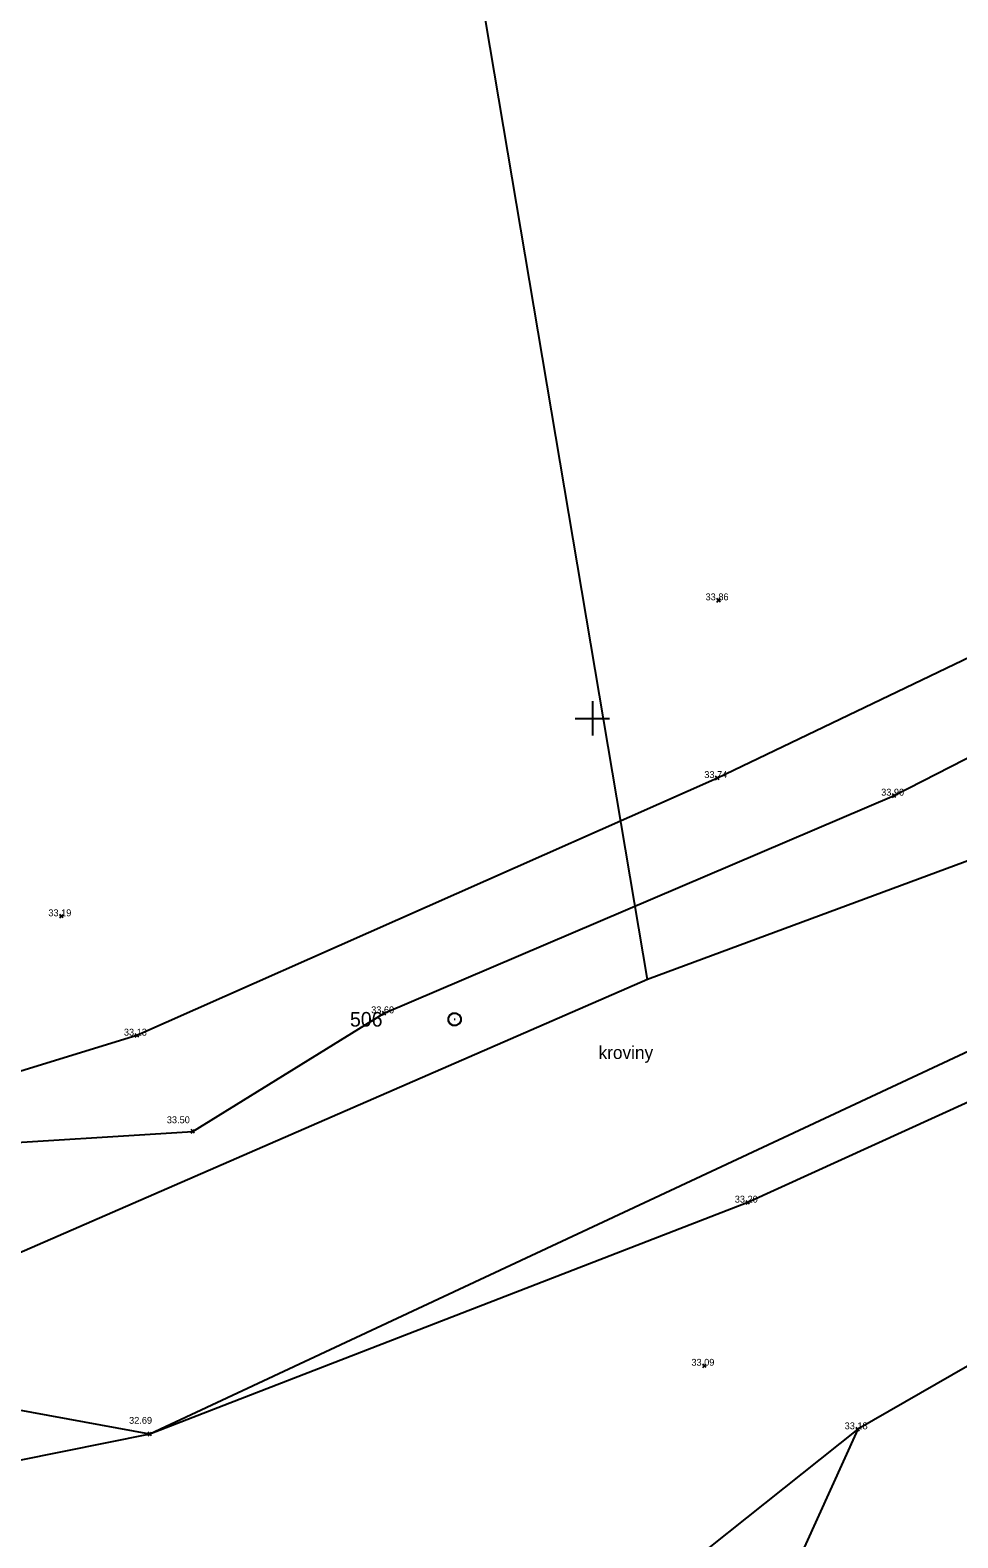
# Model space of a CAD drawing. Extents: x -772865 to -772533, y -1034366 to -1034132.
# Drawn here: x -772813.1 to -772791.49, y -1034294.09 to -1034258.97 of the extents above; entities that cross this region are included whole.
import ezdxf

# ---------------------------------------------------------------- set-up
doc = ezdxf.new("R2010")
doc.units = 0
for name, color, linetype in [('body', 7, 'Continuous'), ('KM_hranice', 7, 'Continuous'), ('KM_mezni_znaky', 7, 'Continuous'), ('mistni_popis', 7, 'Continuous'), ('oddeleni_ploch', 7, 'Continuous'), ('souradnicova_sit', 7, 'Continuous'), ('stromy_kere', 7, 'Continuous'), ('vyskove_koty', 7, 'Continuous')]:
    doc.layers.add(name, color=color, linetype=linetype)

msp = doc.modelspace()

# ---------------------------------------------------------------- linework, layer by layer
at = {"layer": 'body'}
for p, q in [((-772797.02, -1034272.29), (-772797.1, -1034272.21)), ((-772797.1, -1034272.29), (-772797.02, -1034272.21)), ((-772797.05, -1034276.43), (-772797.13, -1034276.35)), ((-772797.13, -1034276.43), (-772797.05, -1034276.35)), ((-772792.93, -1034276.84), (-772793.01, -1034276.76)), ((-772793.01, -1034276.84), (-772792.93, -1034276.76)), ((-772812.33, -1034279.65), (-772812.41, -1034279.57)), ((-772812.41, -1034279.65), (-772812.33, -1034279.57)), ((-772804.81, -1034281.91), (-772804.89, -1034281.83)), ((-772804.89, -1034281.91), (-772804.81, -1034281.83)), ((-772810.57, -1034282.43), (-772810.65, -1034282.35)), ((-772810.65, -1034282.43), (-772810.57, -1034282.35)), ((-772809.27, -1034284.66), (-772809.35, -1034284.58)), ((-772809.35, -1034284.66), (-772809.27, -1034284.58)), ((-772796.34, -1034286.32), (-772796.42, -1034286.24)), ((-772796.42, -1034286.32), (-772796.34, -1034286.24)), ((-772797.35, -1034290.12), (-772797.43, -1034290.04)), ((-772797.43, -1034290.12), (-772797.35, -1034290.04)), ((-772810.27, -1034291.71), (-772810.35, -1034291.63)), ((-772810.35, -1034291.71), (-772810.27, -1034291.63)), ((-772793.78, -1034291.6), (-772793.86, -1034291.52)), ((-772793.86, -1034291.6), (-772793.78, -1034291.52))]:
    msp.add_line(p, q, dxfattribs=at)
at = {"layer": 'KM_hranice'}
for p, q in [((-772798.72, -1034281.08), (-772804.57, -1034246.44)), ((-772778.45, -1034273.57), (-772798.72, -1034281.08)), ((-772798.72, -1034281.08), (-772816.45, -1034288.8))]:
    msp.add_line(p, q, dxfattribs=at)
at = {"layer": 'KM_mezni_znaky'}
msp.add_line((-772803.22, -1034282.01), (-772803.2, -1034282.01), dxfattribs=at)
msp.add_lwpolyline([(-772803.172, -1034281.866), (-772803.104, -1034281.904), (-772803.066, -1034281.972), (-772803.066, -1034282.05), (-772803.104, -1034282.118), (-772803.172, -1034282.156), (-772803.25, -1034282.156), (-772803.318, -1034282.118), (-772803.356, -1034282.05), (-772803.356, -1034281.972), (-772803.318, -1034281.904), (-772803.25, -1034281.866)], close=True, dxfattribs=at)
at = {"layer": 'oddeleni_ploch'}
for points in [[(-772574.1, -1034196.14), (-772586.87, -1034201.34), (-772598.23, -1034205.06), (-772614.53, -1034207.42), (-772626.93, -1034206.95), (-772636.66, -1034207.26), (-772647.96, -1034208.36), (-772659.39, -1034213.08), (-772672.58, -1034218.62), (-772687.49, -1034225.14), (-772703.01, -1034232.02), (-772714.35, -1034236.9), (-772728.88, -1034243.07), (-772737.97, -1034245.74), (-772746.8, -1034246.99), (-772753.85, -1034250.11), (-772762.71, -1034257.3), (-772782.05, -1034269.18), (-772797.09, -1034276.39), (-772810.61, -1034282.39), (-772816.13, -1034284.08), (-772822.76, -1034283.4), (-772826.73, -1034280.27)], [(-772569.67, -1034207.72), (-772578.35, -1034211.18), (-772588.33, -1034216.15), (-772592.11, -1034217.46), (-772598.89, -1034219.1), (-772610.21, -1034219.57), (-772621.14, -1034219.48), (-772637.34, -1034221.06), (-772647.54, -1034222.08), (-772674.34, -1034233.24), (-772685.01, -1034239.21), (-772697.33, -1034242.95), (-772712.12, -1034249.56), (-772725.85, -1034254.8), (-772738.85, -1034261.98), (-772750.37, -1034267.76), (-772764, -1034272.65), (-772783.9, -1034280.59), (-772796.38, -1034286.28), (-772810.31, -1034291.67), (-772823.61, -1034294.35), (-772828.52, -1034296.12), (-772827.01, -1034302.81), (-772823.23, -1034300.75)], [(-772689.63, -1034259.88), (-772704.53, -1034266.45), (-772719.18, -1034273.09), (-772731.59, -1034278.63), (-772738.33, -1034281.57), (-772742.46, -1034279.19), (-772747.03, -1034275.55), (-772755.44, -1034275.22), (-772763.58, -1034277.24), (-772782.03, -1034284.79), (-772793.82, -1034291.56), (-772799.88, -1034296.39), (-772802.42, -1034299.52), (-772804.8, -1034304.37)], [(-772793.82, -1034291.56), (-772795.37, -1034294.98), (-772795.95, -1034300.15)]]:
    msp.add_lwpolyline(points, dxfattribs=at)
at = {"layer": 'souradnicova_sit'}
for p, q in [((-772800, -1034274.6), (-772800, -1034275.4)), ((-772800.4, -1034275), (-772799.6, -1034275))]:
    msp.add_line(p, q, dxfattribs=at)
at = {"layer": 'stromy_kere'}
msp.add_lwpolyline([(-772790.87, -1034282.58), (-772810.31, -1034291.67), (-772814.59, -1034290.89), (-772817.69, -1034287.67), (-772817.57, -1034285.25), (-772814.54, -1034284.95), (-772809.31, -1034284.62), (-772804.85, -1034281.87), (-772792.97, -1034276.8), (-772780.79, -1034270.56)], dxfattribs=at)

# ---------------------------------------------------------------- texts
at = {"layer": 'KM_mezni_znaky'}
msp.add_text('506', height=0.34, dxfattribs=at).set_placement((-772805.649, -1034282.18))
at = {"layer": 'mistni_popis'}
msp.add_text('kroviny', height=0.3, dxfattribs=at).set_placement((-772799.857, -1034282.934))
at = {"layer": 'vyskove_koty'}
for s, p in [('33.86', (-772797.365, -1034272.25)), ('33.74', (-772797.395, -1034276.39)), ('33.90', (-772793.275, -1034276.8)), ('33.19', (-772812.675, -1034279.61)), ('33.60', (-772805.155, -1034281.87)), ('33.13', (-772810.915, -1034282.39)), ('33.50', (-772809.915, -1034284.431)), ('33.20', (-772796.685, -1034286.28)), ('33.09', (-772797.695, -1034290.08)), ('32.69', (-772810.794, -1034291.432)), ('33.18', (-772794.125, -1034291.56))]:
    msp.add_text(s, height=0.16, dxfattribs=at).set_placement(p)

doc.saveas('drawing.dxf')
